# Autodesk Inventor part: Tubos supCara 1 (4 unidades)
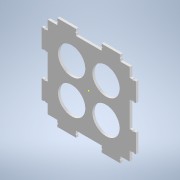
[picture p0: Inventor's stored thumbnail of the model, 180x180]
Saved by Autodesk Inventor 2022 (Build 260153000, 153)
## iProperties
Created: 2022-02
Part Number: Tubos supCara 1 (4 unidades)
Material: Genérico
Document SubType Name: Modeling
Designer: pined
Density: 1 g/cm^3
Appearance: Valor por defecto
Author: pined
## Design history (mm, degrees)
sketch "Boceto1"
  geometry: L1 (-50, -50)-(50, -50); L2 (50, -50)-(50, 50); L3 (50, 50)-(-50, 50); L4 (-50, 50)-(-50, -50); L5 (-50, -50)-(50, 50); L6 (50, -50)-(-50, 50); L7 (-44, 50)-(-44, 45); L8 (-44, 45)-(50, 45); L9 (50, 45)-(45, 45); L10 (-45, -45)-(45, -45); L11 (45, -45)-(45, 45); L12 (45, 45)-(-45, 45); L13 (-45, 45)-(-45, -45); L14 (-45, -45)-(45, 45); L15 (45, -45)-(-45, 45); L16 (-45, 45)-(-35, 45); L17 (-35, 45)-(-35, 50); L18 (-35, 50)-(-15, 50); L19 (-35, 45)-(-35, 47.5); L20 (-35, 47.5)-(-35, 48.3); L21 (-35, 49.1)-(-35, 50); L22 (-25, 50)-(-25, 45); L23 (-15, 45)-(-15, 47.5); L24 (-15, 45)-(-15, 50); L25 (-15, 49.1)-(-15, 50); L26 (-15, 49.1)-(-15, 50.122); L27 (0, 21)-(0, -12); L28 (-10, 0)-(12, 0); L29 (35, 45)-(35, 47.5); L30 (35, 45)-(35, 50); L31 (35, 49.1)-(35, 50); L32 (15, 45)-(15, 50); L33 (15, 45)-(15, 47.5); L34 (15, 49.1)-(15, 50.122); L35 (35, 50)-(15, 50); L36 (-35, -45)-(-35, -50); L37 (-35, -45)-(-35, -47.5); L38 (-35, -49.1)-(-35, -50); L39 (50, -50)-(-50, -50); L40 (-35, -50)-(-15, -50); L41 (-15, -49.1)-(-15, -50.122); L42 (-15, -45)-(-15, -47.5); L43 (15, -45)-(15, -50); L44 (15, -45)-(15, -47.5); L45 (15, -49.1)-(15, -50.122); L46 (35, -50)-(15, -50); L47 (35, -45)-(35, -50); L48 (35, -45)-(35, -47.5); L49 (35, -49.1)-(35, -50); L50 (-45, -35)-(-50, -35); L51 (-49.1, -35)-(-50, -35); L52 (-45, -35)-(-47.5, -35); L53 (-50, 50)-(-50, -50); L54 (-50, -35)-(-50, -15); L55 (-49.1, -15)-(-50.122, -15); L56 (-45, -15)-(-47.5, -15); L57 (-45, 35)-(-50, 35); L58 (-45, 35)-(-47.5, 35); L59 (-49.1, 35)-(-50, 35); L60 (-45, 15)-(-47.5, 15); L61 (-45, 15)-(-50, 15); L62 (-49.1, 15)-(-50.122, 15); L63 (-50, 35)-(-50, 15); L64 (35, -45)-(35, -50)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; A1 r 0.8 centre (-35, 48.3) between (-35, 49.1) and (-35, 47.5); A2 r 0.8 centre (-35, 48.3) between (-35, 47.5) and (-35, 49.1); A3 r 0.8 centre (-15, 48.3) between (-15, 49.1) and (-15, 47.5); A4 r 0.8 centre (35, 48.3) between (35, 49.1) and (35, 47.5); A5 r 0.8 centre (15, 48.3) between (15, 47.5) and (15, 49.1); A6 r 0.8 centre (-35, -48.3) between (-35, -49.1) and (-35, -47.5); A7 r 0.8 centre (-15, -48.3) between (-15, -47.5) and (-15, -49.1); A8 r 0.8 centre (15, -48.3) between (15, -49.1) and (15, -47.5); A9 r 0.8 centre (35, -48.3) between (35, -47.5) and (35, -49.1); A10 r 0.8 centre (-48.3, -35) between (-47.5, -35) and (-49.1, -35); A11 r 0.8 centre (-48.3, -15) between (-49.1, -15) and (-47.5, -15); A12 r 0.8 centre (-48.3, 35) between (-49.1, 35) and (-47.5, 35); A13 r 0.8 centre (-48.3, 15) between (-47.5, 15) and (-49.1, 15); A14 r 0.8 centre (35, -48.3) between (35, -47.5) and (35, -49.1); A15 r 0.8 centre (15, -48.3) between (15, -49.1) and (15, -47.5); A16 r 0.8 centre (-35, -48.3) between (-35, -49.1) and (-35, -47.5); A17 r 0.8 centre (-15, -48.3) between (-15, -47.5) and (-15, -49.1); A18 r 0.8 centre (48.3, 35) between (47.5, 35) and (49.1, 35); A19 r 0.8 centre (48.3, 15) between (49.1, 15) and (47.5, 15); A20 r 0.8 centre (48.3, -35) between (49.1, -35) and (47.5, -35); A21 r 0.8 centre (48.3, -15) between (47.5, -15) and (49.1, -15); 22 further points
  constraints: 206 end point, 42 point on circle, 39 point on line, 37 symmetric about line, 21 centre point, 21 midpoint, 8 perpendicular, 5 parallel, 4 coincident, 3 horizontal, 2 collinear, 1 vertical, 143 other
  dimensions: "d0" = 100 distance of L3.end L2.end; "d1" = 100 distance of L2.end L1.end; "d3" = 5 distance of L8.end L9.end; "d4" = 10 distance of L12.end L16.end; "d5" = 20 distance of L17.end L18.end; "d6" = 2.5 distance of L16.end L19.end; "d7" = 0.8 distance of L19.end L20.end; "d10" = 270 deg dimension on point (0, 0) A1.centre A18.centre; "d24" = 90 distance between parallel lines of L10 L12 (derived)
extrude "Extrusión1" new body sketch "Boceto1" distance "d12" = 2.5; taper "d13" = 0 deg
sketch "Boceto2"
  geometry: 1 further point
sketch "Sketch4"
  geometry: L1 (-43.5, -43.5)-(43.5, -43.5); L2 (43.5, -43.5)-(43.5, 43.5); L3 (43.5, 43.5)-(-43.5, 43.5); L4 (-43.5, 43.5)-(-43.5, -43.5); L5 (-43.5, -43.5)-(43.5, 43.5); L6 (43.5, -43.5)-(-43.5, 43.5); L7 (-35, 45)-(-35, 43.5); L8 (-35, 47.5)-(-35, 45) reference; L9 (-35, 45)-(-45, 45) reference; L10 (-45, 45)-(-45, 35) reference; L11 (-45, 35)-(-47.5, 35) reference; L12 (-49.1, 35)-(-50, 35) reference; L13 (-50, 35)-(-50, 15) reference; L14 (-50, 15)-(-49.1, 15) reference; L15 (-47.5, 15)-(-45, 15) reference; L16 (-45, 15)-(-45, -15) reference; L17 (-45, -15)-(-47.5, -15) reference; L18 (-49.1, -15)-(-50, -15) reference; L19 (-50, -15)-(-50, -35) reference; L20 (-50, -35)-(-49.1, -35) reference; L21 (-47.5, -35)-(-45, -35) reference; L22 (-45, -35)-(-45, -45) reference; L23 (-45, -45)-(-35, -45) reference; L24 (-35, -45)-(-35, -47.5) reference; L25 (-35, -49.1)-(-35, -50) reference; L26 (-35, -50)-(-15, -50) reference; L27 (-15, -50)-(-15, -49.1) reference; L28 (-15, -47.5)-(-15, -45) reference; L29 (-15, -45)-(15, -45) reference; L30 (15, -45)-(15, -47.5) reference; L31 (15, -49.1)-(15, -50) reference; L32 (15, -50)-(35, -50) reference; L33 (35, -50)-(35, -49.1) reference; L34 (35, -47.5)-(35, -45) reference; L35 (35, -45)-(45, -45) reference; L36 (45, -45)-(45, -35) reference; L37 (45, -35)-(47.5, -35) reference; L38 (49.1, -35)-(50, -35) reference; L39 (50, -35)-(50, -15) reference; L40 (50, -15)-(49.1, -15) reference; L41 (47.5, -15)-(45, -15) reference; L42 (45, -15)-(45, 15) reference; L43 (45, 15)-(47.5, 15) reference; L44 (49.1, 15)-(50, 15) reference; L45 (50, 15)-(50, 35) reference; L46 (50, 35)-(49.1, 35) reference; L47 (47.5, 35)-(45, 35) reference; L48 (45, 35)-(45, 45) reference; L49 (45, 45)-(35, 45) reference; L50 (35, 45)-(35, 47.5) reference; L51 (35, 49.1)-(35, 50) reference; L52 (35, 50)-(15, 50) reference; L53 (15, 50)-(15, 49.1) reference; L54 (15, 47.5)-(15, 45) reference; L55 (15, 45)-(-15, 45) reference; L56 (-15, 45)-(-15, 47.5) reference; L57 (-15, 49.1)-(-15, 50) reference; L58 (-15, 50)-(-35, 50) reference; L59 (-35, 50)-(-35, 49.1) reference; L60 (-45, 45)-(-45, 35) reference; L61 (-45, 35)-(-43.5, 35); L62 (-47.5, 15)-(-45, 15) reference; L63 (-45, 15)-(-43.5, 15); L64 (-45, 15)-(-45, -15) reference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; A1 r 0.8 centre (-35, 48.3) between (-35, 47.5) and (-35, 49.1) reference; A2 r 0.8 centre (-48.3, 35) between (-49.1, 35) and (-47.5, 35) reference; A3 r 0.8 centre (-48.3, 15) between (-47.5, 15) and (-49.1, 15) reference; A4 r 0.8 centre (-48.3, -15) between (-49.1, -15) and (-47.5, -15) reference; A5 r 0.8 centre (-48.3, -35) between (-47.5, -35) and (-49.1, -35) reference; A6 r 0.8 centre (-35, -48.3) between (-35, -49.1) and (-35, -47.5) reference; A7 r 0.8 centre (-15, -48.3) between (-15, -47.5) and (-15, -49.1) reference; A8 r 0.8 centre (15, -48.3) between (15, -49.1) and (15, -47.5) reference; A9 r 0.8 centre (35, -48.3) between (35, -47.5) and (35, -49.1) reference; A10 r 0.8 centre (48.3, -35) between (49.1, -35) and (47.5, -35) reference; A11 r 0.8 centre (48.3, -15) between (47.5, -15) and (49.1, -15) reference; A12 r 0.8 centre (48.3, 15) between (49.1, 15) and (47.5, 15) reference; A13 r 0.8 centre (48.3, 35) between (47.5, 35) and (49.1, 35) reference; A14 r 0.8 centre (35, 48.3) between (35, 49.1) and (35, 47.5) reference; A15 r 0.8 centre (15, 48.3) between (15, 47.5) and (15, 49.1) reference; A16 r 0.8 centre (-15, 48.3) between (-15, 49.1) and (-15, 47.5) reference; 2 further points
  constraints: 44 end point, 19 point on line, 13 perpendicular, 2 midpoint, 2 parallel, 1 horizontal, 1 vertical
  dimensions: "d25" = 87 distance of L3.end L2.end; "d26" = 87 distance of L2.end L1.end
extrude "Extrusion3" cut sketch "Sketch4" distance "d27" = 10; taper "d28" = 0 deg
sketch "Sketch5"
  geometry: L1 (-49.1, 35)-(-47.5, 35); L2 (-47.5, 35)-(-43.5, 35) reference; L3 (-50, 35)-(-50, 15) reference; L4 (-43.5, 35)-(-50, 35); L5 (-50, 35)-(-50, 15); L6 (-50, 15)-(-43.5, 15); L7 (-43.5, 15)-(-43.5, 35); L8 (-15, 50)-(-35, 50) reference; L9 (-35, 43.5)-(-43.5, 43.5) reference; L10 (-15, 50)-(-35, 50); L11 (-35, 50)-(-35, 43.5); L12 (-35, 43.5)-(-15, 43.5); L13 (-15, 43.5)-(-15, 50); L14 (15, 47.5)-(15, 43.5) reference; L15 (35, 50)-(15, 50) reference; L16 (15, 43.5)-(35, 43.5); L17 (35, 43.5)-(35, 50); L18 (35, 50)-(15, 50); L19 (15, 50)-(15, 43.5); L20 (47.5, 35)-(43.5, 35) reference; L21 (49.1, 15)-(50, 15) reference; L22 (43.5, 35)-(50, 35); L23 (50, 35)-(50, 15); L24 (50, 15)-(43.5, 15); L25 (43.5, 15)-(43.5, 35); L26 (47.5, -15)-(43.5, -15) reference; L27 (43.5, -15)-(50, -15); L28 (50, -15)-(50, -35); L29 (50, -35)-(43.5, -35); L30 (43.5, -35)-(43.5, -15); L31 (35, -43.5)-(43.5, -43.5) reference; L32 (15, -50)-(35, -50) reference; L33 (35, -43.5)-(15, -43.5); L34 (15, -43.5)-(15, -50); L35 (15, -50)-(35, -50); L36 (35, -50)-(35, -43.5); L37 (-15, -43.5)-(15, -43.5) reference; L38 (-35, -50)-(-15, -50) reference; L39 (-15, -43.5)-(-35, -43.5); L40 (-35, -43.5)-(-35, -50); L41 (-35, -50)-(-15, -50); L42 (-15, -50)-(-15, -43.5); L43 (-47.5, -35)-(-43.5, -35) reference; L44 (-49.1, -15)-(-50, -15) reference; L45 (-43.5, -35)-(-50, -35); L46 (-50, -35)-(-50, -15); L47 (-50, -15)-(-43.5, -15); L48 (-43.5, -15)-(-43.5, -35); A1 r 0.8 centre (-48.3, 35) between (-49.1, 35) and (-47.5, 35) reference; 13 further points
  constraints: 66 end point, 16 parallel, 9 horizontal, 8 perpendicular, 1 point on line
extrude "Extrusion4" join sketch "Sketch5" distance "d29" = 2.5; taper "d30" = 0 deg
sketch "Sketch6"
  geometry: L1 (-35, 43.5)-(-35, 46.8); L2 (-35, 50)-(-35, 43.5) reference; L3 (-35, 46.8)-(40.671, 46.8); L4 (35, 43.5)-(35, 50) reference; L5 (-15, 43.5)-(-15, 50) reference; L6 (15, 50)-(15, 43.5) reference; L7 (0, 0)-(22.296, 0); L8 (-43.5, 35)-(-46.8, 35); L9 (-43.5, 35)-(-50, 35) reference; L10 (-46.8, 35)-(-46.8, -41.122); L11 (-50, 15)-(-43.5, 15) reference; L12 (-43.5, -15)-(-50, -15) reference; L13 (-50, -35)-(-43.5, -35) reference; L14 (0, 0)-(0, 10.489); C1 r 0.8 at (-35, 46.8); C2 r 0.8 at (-15, 46.75); C3 r 0.8 at (15, 46.75); C4 r 0.8 at (35, 46.75); C5 r 0.8 at (-15, -46.75); C6 r 0.8 at (-35, -46.8); C7 r 0.8 at (15, -46.75); C8 r 0.8 at (35, -46.75); C9 r 0.8 at (-46.8, 35); C10 r 0.8 at (-46.75, 15); C11 r 0.8 at (-46.75, -15); C12 r 0.8 at (-46.75, -35); C13 r 0.8 at (46.8, 35); C14 r 0.8 at (46.75, 15); C15 r 0.8 at (46.75, -15); C16 r 0.8 at (46.75, -35); 4 further points
  constraints: 16 centre point, 12 end point, 8 symmetric about line, 6 midpoint, 2 coincident, 2 perpendicular, 2 point on line, 1 horizontal, 1 vertical, 8 other
  dimensions: "d31" = 3.3 distance of L1.start L1.end; "d32" = 1.6 diameter of C1; "d33" = 1.6 diameter of C2; "d34" = 1.6 diameter of C3; "d35" = 1.6 diameter of C4; "d36" = 3.3 distance of L8.start L8.end; "d37" = 1.6 diameter of C9; "d38" = 1.6 diameter of C10; "d39" = 1.6 diameter of C11; "d40" = 1.6 diameter of C12
extrude "Extrusion5" cut sketch "Sketch6" distance "d41" = 2.5; taper "d42" = 0 deg
sketch "Sketch7"
  geometry: L1 (-35, 43.5)-(-43.5, 43.5) reference; L2 (-35, 50)-(-15, 50) reference; L3 (-43.5, 43.5)-(-33.5, 43.5); L4 (-33.5, 43.5)-(-33.5, 50); L5 (-33.5, 50)-(-43.5, 50); L6 (-43.5, 50)-(-43.5, 43.5); L7 (15, 50)-(35, 50) reference; L8 (43.5, 43.5)-(33.5, 43.5); L9 (33.5, 43.5)-(33.5, 50); L10 (33.5, 50)-(43.5, 50); L11 (43.5, 50)-(43.5, 43.5); L12 (-50, 15)-(-50, 35) reference; L13 (-43.5, 43.5)-(-50, 43.5); L14 (-50, 43.5)-(-50, 33.5); L15 (-50, 33.5)-(-43.5, 33.5); L16 (-43.5, 33.5)-(-43.5, 43.5); L17 (-43.5, -43.5)-(-35, -43.5) reference; L18 (-50, -35)-(-50, -15) reference; L19 (-43.5, -43.5)-(-50, -43.5); L20 (-50, -43.5)-(-50, -33.5); L21 (-50, -33.5)-(-43.5, -33.5); L22 (-43.5, -33.5)-(-43.5, -43.5); L23 (-43.5, -43.5)-(-33.5, -43.5); L24 (-33.5, -43.5)-(-33.5, -50); L25 (-33.5, -50)-(-43.5, -50); L26 (-43.5, -50)-(-43.5, -43.5); L27 (43.5, -43.5)-(43.5, -35) reference; L28 (35, -50)-(15, -50) reference; L29 (43.5, -43.5)-(33.5, -43.5); L30 (33.5, -43.5)-(33.5, -50); L31 (33.5, -50)-(43.5, -50); L32 (43.5, -50)-(43.5, -43.5); L33 (50, -15)-(50, -35) reference; L34 (43.5, -43.5)-(50, -43.5); L35 (50, -43.5)-(50, -33.5); L36 (50, -33.5)-(43.5, -33.5); L37 (43.5, -33.5)-(43.5, -43.5); L38 (50, 35)-(50, 15) reference; L39 (43.5, 43.5)-(50, 43.5); L40 (50, 43.5)-(50, 33.5); L41 (50, 33.5)-(43.5, 33.5); L42 (43.5, 33.5)-(43.5, 43.5); 11 further points
  constraints: 64 end point, 16 parallel, 8 horizontal, 8 perpendicular, 7 point on line
  dimensions: "d43" = 10 distance of L5.end L4.end; "d44" = 10 distance of L9.end L10.end; "d45" = 10 distance of L14.end L13.end; "d46" = 10 distance of L19.end L20.end; "d47" = 6.5 distance of L23.end L24.end; "d48" = 10 distance of L31.end L30.end; "d49" = 10 distance of L35.end L34.end; "d50" = 10 distance of L39.end L40.end
extrude "Extrusion6" cut sketch "Sketch7" distance "d51" = 10; taper "d52" = 0 deg
sketch "Sketch8"
  geometry: L1 (-33.5, 50)-(-15, 50) reference; L2 (-15, 43.5)-(15, 43.5) reference; L3 (-33.5, 50)-(-13.5, 50); L4 (-13.5, 50)-(-13.5, 43.5); L5 (-13.5, 43.5)-(-33.5, 43.5); L6 (-33.5, 43.5)-(-33.5, 50); L7 (15, 50)-(33.5, 50) reference; L8 (33.5, 50)-(13.5, 50); L9 (13.5, 50)-(13.5, 43.5); L10 (13.5, 43.5)-(33.5, 43.5); L11 (33.5, 43.5)-(33.5, 50); L12 (50, 33.5)-(50, 15) reference; L13 (43.5, -15)-(43.5, 15) reference; L14 (50, 33.5)-(43.5, 33.5); L15 (43.5, 33.5)-(43.5, 13.5); L16 (43.5, 13.5)-(50, 13.5); L17 (50, 13.5)-(50, 33.5); L18 (50, -15)-(50, -33.5) reference; L19 (50, -33.5)-(43.5, -33.5); L20 (43.5, -33.5)-(43.5, -13.5); L21 (43.5, -13.5)-(50, -13.5); L22 (50, -13.5)-(50, -33.5); L23 (33.5, -43.5)-(43.5, -43.5) reference; L24 (33.5, -43.5)-(13.5, -43.5); L25 (13.5, -43.5)-(13.5, -50); L26 (13.5, -50)-(33.5, -50); L27 (33.5, -50)-(33.5, -43.5); L28 (-43.5, -43.5)-(-33.5, -43.5) reference; L29 (-33.5, -43.5)-(-13.5, -43.5); L30 (-13.5, -43.5)-(-13.5, -50); L31 (-13.5, -50)-(-33.5, -50); L32 (-33.5, -50)-(-33.5, -43.5); L33 (-50, -33.5)-(-43.5, -33.5) reference; L34 (-43.5, 15)-(-43.5, -15) reference; L35 (-50, -33.5)-(-43.5, -33.5); L36 (-43.5, -33.5)-(-43.5, -13.5); L37 (-43.5, -13.5)-(-50, -13.5); L38 (-50, -13.5)-(-50, -33.5); L39 (-50, 15)-(-50, 33.5) reference; L40 (-50, 33.5)-(-43.5, 33.5); L41 (-43.5, 33.5)-(-43.5, 13.5); L42 (-43.5, 13.5)-(-50, 13.5); L43 (-50, 13.5)-(-50, 33.5); 16 further points
  constraints: 64 end point, 16 parallel, 8 horizontal, 8 perpendicular, 6 point on line
  dimensions: "d53" = 20 distance of L4.end L5.end; "d54" = 20 distance of L10.end L9.end; "d55" = 20 distance of L15.end L14.end; "d56" = 6.5 distance of L20.end L21.end; "d57" = 20 distance of L19.end L20.end; "d58" = 20 distance of L26.end L25.end; "d59" = 20 distance of L30.end L31.end; "d60" = 20 distance of L36.end L35.end; "d61" = 20 distance of L40.end L41.end
extrude "Extrusion7" join sketch "Sketch8" distance "d62" = 2.5; taper "d63" = 0 deg
sketch "Sketch9"
  geometry: L1 (-33.5, 50)-(-33.5, 43.5) reference; L2 (-33.5, 43.5)-(-33.5, 46.8); L3 (-33.5, 46.8)-(40.435, 46.8); L4 (-43.5, 43.5)-(-43.5, 33.5) reference; L5 (-43.5, 33.5)-(-46.8, 33.5); L6 (-43.5, 33.5)-(-50, 33.5) reference; L7 (-46.8, 33.5)-(-46.8, -49.655); L8 (33.5, 43.5)-(33.5, 50) reference; L9 (13.5, 50)-(13.5, 43.5) reference; L10 (-13.5, 50)-(-13.5, 43.5) reference; L11 (-43.5, 13.5)-(-50, 13.5) reference; L12 (-43.5, -13.5)-(-50, -13.5) reference; L13 (-43.5, -33.5)-(-50, -33.5) reference; L14 (0, 0)-(13.5, 0); L15 (13.5, 0)-(0, 0); L16 (0, 0)-(0, 17.379); C1 r 0.8 at (33.5, 46.75); C2 r 0.8 at (13.5, 46.75); C3 r 0.8 at (-13.5, 46.75); C4 r 0.8 at (-33.5, 46.8); C5 r 0.8 at (-46.8, 33.5); C6 r 0.8 at (-46.75, 13.5); C7 r 0.8 at (-46.75, -13.5); C8 r 0.8 at (-46.75, -33.5); C9 r 0.8 at (-33.5, -46.8); C10 r 0.8 at (-13.5, -46.75); C11 r 0.8 at (13.5, -46.75); C12 r 0.8 at (33.5, -46.75); C13 r 0.8 at (46.8, 33.5); C14 r 0.8 at (46.75, 13.5); C15 r 0.8 at (46.75, -13.5); C16 r 0.8 at (46.75, -33.5); 10 further points
  constraints: 16 centre point, 14 end point, 8 symmetric about line, 6 midpoint, 2 coincident, 2 perpendicular, 2 point on line, 1 collinear, 1 horizontal, 1 vertical, 8 other
  dimensions: "d64" = 3.3 distance of L1.end L2.end; "d65" = 3.3 distance of L4.end L5.end; "d66" = 1.6 diameter of C1; "d67" = 1.6 diameter of C2; "d68" = 1.6 diameter of C3; "d69" = 1.6 diameter of C4; "d70" = 1.6 diameter of C5; "d71" = 1.6 diameter of C6; "d72" = 1.6 diameter of C7; "d73" = 1.6 diameter of C8
extrude "Extrusion8" cut sketch "Sketch9" distance "d74" = 2.5; taper "d75" = 0 deg
sketch "Sketch10"
  geometry: C1 r 6.5 at (18.214, -18.214) reference; C2 r 6.5 at (-18.214, -18.214) reference; C3 r 6.5 at (-18.214, 18.214) reference; C4 r 6.5 at (18.214, 18.214) reference; C5 r 14.5 at (18.214, -18.214); C6 r 14.5 at (-18.214, -18.214); C7 r 14.5 at (18.214, 18.214); C8 r 14.5 at (-18.214, 18.214); 1 further point
  constraints: 4 centre point, 4 coincident
  dimensions: "d76" = 29 diameter of C5; "d77" = 29 diameter of C6; "d78" = 29 diameter of C7; "d79" = 29 diameter of C8
extrude "Extrusion9" cut sketch "Sketch10" distance "d80" = 10; taper "d81" = 0 deg
node "Sólido1"
node "Projected Loop1"
node "Reference1"
node "Reference2"
node "Reference3"
node "Reference4"
